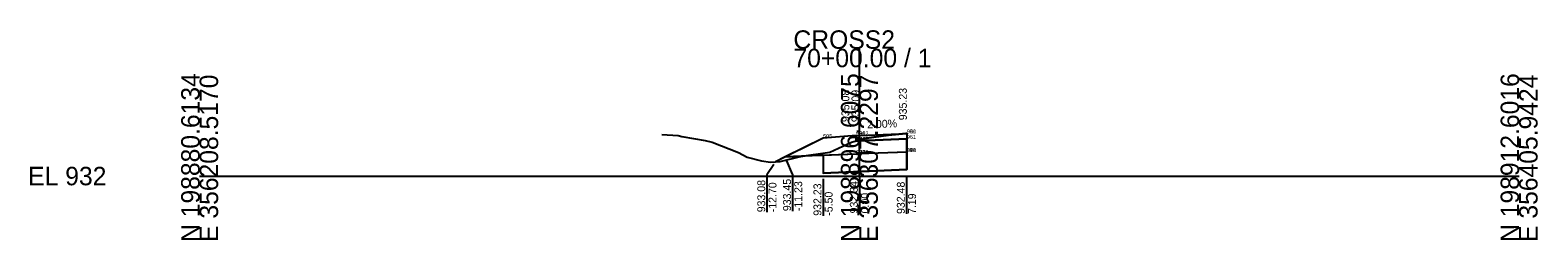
# Model space of a CAD drawing. Extents: x -26 to 203, y -10 to 14021.
# Drawn here: x -25.7 to 202.8, y 10990.3 to 11022.2 of the extents above; entities that cross this region are included whole.
import ezdxf

# ---------------------------------------------------------------- set-up
doc = ezdxf.new("R2010")
doc.units = 0
for name, color, linetype in [('Default', 7, 'Continuous'), ('P_E_XS_Ground', 7, 'Continuous'), ('P_XS', 7, 'Continuous'), ('P_XS_Bold', 7, 'Continuous'), ('P_XS_EAR_CommonGrnd', 7, 'Continuous'), ('P_XS_Lane', 7, 'Continuous'), ('P_XS_Rock', 7, 'Continuous')]:
    doc.layers.add(name, color=color, linetype=linetype)

msp = doc.modelspace()

# ---------------------------------------------------------------- linework, layer by layer
at = {"layer": 'Default'}
for p, q in [((100, 11000), (100, 11019.32)), ((0, 11000), (100, 11000)), ((100, 11000), (200, 11000))]:
    msp.add_line(p, q, dxfattribs=at)
at = {"layer": 'P_E_XS_Ground'}
for p, q in [((70.04, 11006.31), (72.51, 11006.15)), ((72.51, 11006.15), (73.08, 11005.98)), ((101.08, 11005.77), (104.39, 11006.23)), ((104.39, 11006.23), (107.04, 11006.44)), ((107.04, 11006.44), (107.27, 11006.49)), ((73.08, 11005.98), (76.62, 11005.42)), ((76.62, 11005.42), (77.66, 11005.14)), ((77.66, 11005.14), (81.68, 11003.56)), ((95.5, 11003.63), (98.79, 11005.14)), ((98.79, 11005.14), (100, 11005.47)), ((100, 11005.47), (101.08, 11005.77)), ((81.68, 11003.56), (82.97, 11002.85)), ((82.97, 11002.85), (85.17, 11002.3)), ((85.17, 11002.3), (86.52, 11002.09)), ((86.52, 11002.09), (87.97, 11002.22)), ((87.97, 11002.22), (91.06, 11002.97)), ((91.06, 11002.97), (95.5, 11003.63))]:
    msp.add_line(p, q, dxfattribs=at)
at = {"layer": 'P_XS'}
for p, q in [((99.5, 11006.16), (99.5, 11005.33)), ((107.19, 11006.47), (107.19, 11005.64)), ((99.5, 11005.33), (100, 11005.35)), ((107.19, 11005.64), (99.99, 11005.35)), ((107.19, 11003.64), (107.19, 11005.64)), ((99.5, 11003.33), (88.77, 11002.9)), ((94.5, 11003.13), (94.5, 11000.46)), ((99.5, 11003.33), (100, 11003.35)), ((107.19, 11003.64), (99.99, 11003.35)), ((107.19, 11003.64), (107.19, 11000.97)), ((107.19, 11000.97), (94.5, 11000.46))]:
    msp.add_line(p, q, dxfattribs=at)
at = {"layer": 'P_XS_EAR_CommonGrnd'}
for points in [[(94.5, 11005.76), (88.77, 11002.9), (91.23, 11003), (95.5, 11003.63), (98.79, 11005.14), (99.5, 11005.33), (99.5, 11006.16)], [(101.08, 11005.77), (104.39, 11006.23), (107.04, 11006.44), (107.19, 11006.47), (107.19, 11005.64), (100, 11005.35), (99.5, 11005.33), (100, 11005.47)], [(100, 11006.18), (107.19, 11006.47), (107.04, 11006.44), (104.39, 11006.23), (101.08, 11005.77), (100, 11005.47), (99.5, 11005.33), (99.5, 11006.16)], [(107.19, 11003.64), (100, 11003.35), (99.5, 11003.33), (94.5, 11003.13), (91.23, 11003), (95.5, 11003.63), (98.79, 11005.14), (99.5, 11005.33), (100, 11005.35), (107.19, 11005.64)], [(88.77, 11002.9), (87.3, 11002.16), (87.97, 11002.22), (91.06, 11002.97), (91.23, 11003)], [(107.19, 11003.64), (100, 11003.35), (99.5, 11003.33), (94.5, 11003.13), (94.5, 11000.46), (107.19, 11000.97)]]:
    msp.add_lwpolyline(points, close=True, dxfattribs=at)
at = {"layer": 'P_XS_Lane'}
for p, q in [((99.5, 11006.16), (94.5, 11005.76)), ((99.5, 11006.16), (100, 11006.18)), ((100, 11006.18), (107.19, 11006.47)), ((94.5, 11005.76), (87.3, 11002.16))]:
    msp.add_line(p, q, dxfattribs=at)
at = {"layer": 'P_XS_Rock'}
for p, q in [((87.03, 11001.77), (85.98, 11000.19)), ((89.88, 11000.27), (89.02, 11002.32)), ((85.98, 11000.19), (85.98, 10994.5)), ((89.88, 11000.27), (89.88, 10994.67)), ((94.49, 10999.56), (94.49, 10993.96)), ((100.01, 10999.93), (100.01, 10994.33)), ((107.13, 10999.83), (107.13, 10994.24))]:
    msp.add_line(p, q, dxfattribs=at)

# ---------------------------------------------------------------- texts
at = {"layer": 'Default'}
for s, p in [('CROSS2', (90, 11019.32)), ('70+00.00 / 1', (90, 11016.52)), ('EL 932', (-26, 10998.6))]:
    msp.add_text(s, height=2.8, dxfattribs=at).set_placement(p)
for s, p in [('N 198880.6134', (0, 10990)), ('N 198896.6075', (100, 10990)), ('N 198912.6016', (200, 10990)), ('E 356405.9424', (202.8, 10990)), ('E 356208.5170', (2.8, 10990)), ('E 356307.2297', (102.8, 10990))]:
    msp.add_text(s, height=2.8, rotation=90, dxfattribs=at).set_placement(p)
at = {"layer": 'P_XS_Bold'}
for s, p in [('505', (94.5, 11005.76)), ('951', (99.5, 11006.16)), ('9', (99.5, 11006.16)), ('900', (99.5, 11006.16)), ('952', (100, 11006.18)), ('952', (100, 11006.18)), ('951', (107.19, 11006.47)), ('9', (107.19, 11006.47)), ('900', (107.19, 11006.47)), ('910', (107.19, 11006.47)), ('961', (107.19, 11005.64)), ('961', (99.5, 11005.33)), ('971', (99.5, 11003.33)), ('998', (99.5, 11003.33)), ('962', (99.99, 11005.35)), ('972', (99.99, 11003.35)), ('962', (100, 11005.35)), ('972', (100, 11003.35)), ('540', (107.19, 11003.64)), ('971', (107.19, 11003.64)), ('998', (107.19, 11003.64))]:
    msp.add_text(s, height=0.6, dxfattribs=at).set_placement(p)
at = {"layer": 'P_XS_Rock'}
for s, rotation, p in [('935.08', 90, (98.48, 11008.2)), ('935.09', 90, (100, 11008.18)), ('935.09', 90, (100, 11008.18)), ('935.09', 90, (100, 11008.18)), ('935.09', 90, (100, 11008.18)), ('935.23', 90, (107.19, 11008.47)), ('2.00%', 2.2906, (101.19, 11007.23)), ('933.08', 90, (85.73, 10994.5)), ('933.45', 90, (89.63, 10994.67)), ('-12.70', 90, (87.43, 10994.5)), ('-11.23', 90, (91.33, 10994.67)), ('932.23', 90, (94.24, 10993.97)), ('-5.50', 90, (95.94, 10993.97)), ('932.34', 90, (99.76, 10994.33)), ('0.00', 90, (101.46, 10994.33)), ('932.48', 90, (106.88, 10994.24)), ('7.19', 90, (108.58, 10994.24))]:
    msp.add_text(s, height=1.2, rotation=rotation, dxfattribs=at).set_placement(p)

doc.saveas('drawing.dxf')
